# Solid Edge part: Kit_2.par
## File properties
Sűrűség: 0,000 kg/m^3
Pontosság: 0,990
Author: bmolnar
Last saved by: bmolnar
Revision: 77
Username: bmolnar
Dokumentum tartalom típus: 0
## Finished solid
Body 1: solid body, 21 faces, 37 edges, 27 vertices.
  Faces by surface: plane 11, cylinder 8, cone 1, torus 1
  Edges by curve: circle 19, line 18
Bounding box of the edges (mm; curved faces can reach further): 29.400 x 28.800 x 3.500, from (-14.7, -13.45, 0.2) to (14.7, 15.35, 3.7).
Cylindrical faces by radius (mm): R1 x2, R1.8 x2, R8.75 x1, R12.9833 x1, R13.45 x1, R14.7 x1
Conical faces (half-angle, radius in mm at the cone's reference point): 45 deg R8.5 x1
Toroidal faces (ring radius, tube radius in mm): R9.15 r0.4 x1
Planar faces by outward normal: +z 2, -z 5, oblique 4
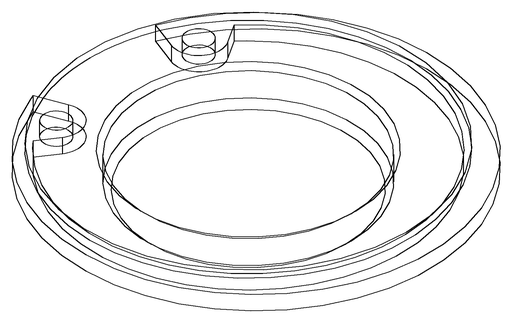
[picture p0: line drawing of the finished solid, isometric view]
